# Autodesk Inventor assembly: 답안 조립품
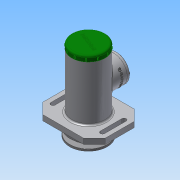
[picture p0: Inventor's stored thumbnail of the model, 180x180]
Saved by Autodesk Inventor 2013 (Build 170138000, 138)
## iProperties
Created: 2017-10
Part Number: 답안 조립품
Document SubType Name: Assembly
Designer: Administrator
Author: Administrator
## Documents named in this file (20)
- C:\Users\Administrator\Desktop\471008V1013\답안 조립품.iam
- C:\Users\Administrator\Desktop\471008V1013\본체.ipt
- C:\Users\Administrator\Desktop\471008V1013\V-벨트풀리.ipt
- C:\Users\Administrator\Desktop\471008V1013\너트 M10.ipt
- C:\Users\Administrator\Desktop\471008V1013\멈춤링 15 x 1.ipt
- C:\Users\Administrator\Desktop\471008V1013\멈춤링 35x1.6.ipt
- C:\Users\Administrator\Desktop\471008V1013\베어링 15 x 35 x 11.ipt
- C:\Users\Administrator\Desktop\471008V1013\볼트 M4 x 10.ipt
- C:\Users\Administrator\Desktop\471008V1013\부시1.ipt
- C:\Users\Administrator\Desktop\471008V1013\부시2.ipt
- C:\Users\Administrator\Desktop\471008V1013\사이드 커버.ipt
- 사이드 커버.ipt
- C:\Users\Administrator\Desktop\471008V1013\십자볼트 M3 x 10.ipt
- C:\Users\Administrator\Desktop\471008V1013\오일 실 15 25 7.ipt
- C:\Users\Administrator\Desktop\471008V1013\와셔 3x6.ipt
- C:\Users\Administrator\Desktop\471008V1013\와셔 4x16.ipt
- C:\Users\Administrator\Desktop\471008V1013\와셔 10x21.ipt
- C:\Users\Administrator\Desktop\471008V1013\축.ipt
- C:\Users\Administrator\Desktop\471008V1013\키 4 x 4 x 18.ipt
- C:\Users\Administrator\Desktop\471008V1013\탑 커버.ipt
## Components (2 placed, 2 different names)
1. V-벨트풀리:1
2. ISO 4017 M4 x 10:1
